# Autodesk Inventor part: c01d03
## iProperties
Created: 2004-05
Part Number: c01d03
Document SubType Name: Modeling
Designer: CADCIM Technologies
Manufacturer: Standard
Standards Organization: Custom
Author: CADCIM Technologies
